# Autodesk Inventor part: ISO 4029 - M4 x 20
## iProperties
Comments: To add or edit properties for Autodesk Inventor files, use iProperties.
Created: 2004-08
Part Number: ISO 4029 - M4 x 20
Vendor: Autodesk Inc.
Document SubType Name: Modeling
Designer: John Blackburn
Material: Default
Description: Hexagon Socket Set Screw
Standard: ISO 4029
Size Designation: M4 x 20
Alert: To add or edit properties for Autodesk Inventor files, use iProperties.
Control State: 0
Master: False
Checked Out: False
Shininess: 64.0
Length Units: 11269
Angle Units: 11279
Time Units: 11290
Mass Units: 11283
Length Display Precision: 3
Angle Display Precision: 2
Compacted: True
EGR: 1
Density: 0.0
Volumn: 0.0
Area: 0.0
PropertySet Name: Model Information
Author: John Blackburn
Revision Number: 8
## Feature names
1. Body [Revolution]
2. Slot [Extrusion]
3. Chamfer1
4. Chamfer2
